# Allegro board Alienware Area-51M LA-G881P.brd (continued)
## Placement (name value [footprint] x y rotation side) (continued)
CT79  1U_0201_6.3V6M  [C_0201]  25.6 44.43 180 top
CT80  1U_0201_6.3V6M  [C_0201]  24.9 43.1 90 top
CT81  10U_0402_6.3V6M  [C_0402]  20.36 40.22 180 top
CT82  10U_0402_6.3V6M  [C_0402]  19.84 39.15 270 top
CT83  1U_0201_6.3V6M  [C_0201]  22.38 43.3 270 top
CT84  1U_0201_6.3V6M  [C_0201]  21.11 40.43 270 top
CT85  1U_0201_6.3V6M  [C_0201]  23.09 39.9 0 top
CT86  1U_0201_6.3V6M  [C_0201]  23.02 41.37 270 top
CT88  0.1U_0402_10V6K  [C_0402]  39.08 48.25 180 top
CT90  22U_0603_6.3V6M  [C_0603]  46.93 41.95 180 bottom
CT91  22U_0603_6.3V6M  [C_0603]  46.93 40.68 180 bottom
CT92  22U_0603_6.3V6M  [C_0603]  46.93 39.41 180 bottom
CT93  22U_0603_6.3V6M  [C_0603]  46.93 38.14 180 bottom
CT94  0.47U_0402_25V6K  [C_0402]  8.35 48.49 270 bottom
CT95  0.47U_0402_25V6K  [C_0402]  9.87 48.49 270 bottom
CT96  0.47U_0402_25V6K  [C_0402]  9.75 44.19 0 bottom
CT97  0.47U_0402_25V6K  [C_0402]  9.75 44.19 0 top
CT98  2.2U_0402_16V6K  [C_0402]  38.21 45.36 180 bottom
CT99  4.7U_0603_10V6K  [C_0603]  39.13 42.16 270 bottom
CT100  4.7U_0603_10V6K  [C_0603]  38.88 52.32 180 bottom
CT101  10U_0402_6.3V6M  [C_0402]  39.08 49.14 180 top
CT102  1U_0201_6.3V6M  [C_0201]  38.88 48.73 180 bottom
CT103  10U_0402_6.3V6M  [C_0402]  39.03 47.97 180 bottom
CT104  0.22U_0402_10V6K  [C_0402]  44.55 47.94 270 top
CT106  1U_0603_25V6K  [C_0603]  47.08 47.39 0 top
CT108  0.22U_0201_6.3V  [C_0201]  23.68 35.21 90 bottom
CT109  0.22U_0201_6.3V  [C_0201]  24.31 35.21 90 bottom
CT110  0.22U_0201_6.3V  [C_0201]  21.14 35.21 90 bottom
CT111  0.22U_0201_6.3V  [C_0201]  21.77 35.21 90 bottom
CT112  220P_0201_25V7K  [C_0201]  46.88 52.34 90 bottom
CT113  220P_0201_25V7K  [C_0201]  48.05 52.37 90 bottom
CT114  100P_0402_50V8J~D  [C_0402]  88.57 19.4 90 bottom
CT115  0.047U_0402_25V7K  [C_0402]  80.72 8.94 90 top
CT116  10U_0603_6.3V6M~D  [C_0603]  93.55 18.55 270 bottom
CT117  2200P_0402_25V7K  [C_0402]  93.44 19.44 90 bottom
CT118  0.1U_0402_10V6K  [C_0402]  94.67 18.64 270 bottom
CT121  0.1U_0402_16V7K  [C_0402]  60.34 23.58 0 top
CT122  4.7U_0805_10V4Z  [C_0805]  60.08 22.25 0 top
CT123  0.1U_0402_16V7K  [C_0402]  58.96 21.31 270 top
CT124  22U_0603_6.3V6M  [C_0603]  56.54 25.8 0 top
CT153  1U_0201_6.3V6M  [C_0201]  31.38 36.38 270 bottom
CT154  47U_0603_6.3V6M  [C_0603]  32.29 36.79 270 bottom
CT155  47U_0603_6.3V6M  [C_0603]  33.56 36.79 270 bottom
CT156  22P_0402_50V8J~D  [C_0402]  47.01 35.23 0 bottom
CT157  4.7U_0603_10V6K  [C_0603]  49.16 44.55 0 bottom
CT200  0.1U_0402_10V7K  [C_0402]  43.57 24.85 0 bottom
CT201  0.1U_0402_10V7K  [C_0402]  49.44 25.23 180 bottom
CT202  0.1U_0402_10V7K  [C_0402]  49.43 27.77 180 bottom
CT203  0.1U_0402_10V7K  [C_0402]  47.01 20.46 90 bottom
CT204  0.1U_0402_10V7K  [C_0402]  43.57 25.74 0 bottom
CT205  1U_0201_6.3V6M  [C_0201]  46.07 30.77 0 bottom
CT206  10U_0603_6.3V6M  [C_0603]  46.13 28.79 270 bottom
CT207  10U_0603_6.3V6M  [C_0603]  44.91 29.68 270 bottom
CT208  1U_0201_6.3V6M  [C_0201]  43.98 29.68 270 bottom
CT209  0.1U_0402_10V7K  [C_0402]  47.55 12.81 270 top
CT210  0.1U_0402_10V7K  [C_0402]  48.5 12.81 270 top
CT211  0.01U_0402_16V7K  [C_0402]  61.29 12.53 0 top
CT212  0.01U_0402_16V7K  [C_0402]  61.29 11.64 0 top
CT213  1U_0201_6.3V6M  [C_0201]  58.17 10.75 270 top
CT214  0.1U_0402_10V7K  [C_0402]  59.08 16.61 270 top
CT215  0.1U_0402_10V7K  [C_0402]  58.19 16.61 270 top
CT216  22U_0603_6.3V6M  [C_0603]  61.43 15.64 180 top
CT217  1U_0201_6.3V6M  [C_0201]  46.07 30.2 0 bottom
CT218  1U_0201_6.3V6M  [C_0201]  44.75 30.52 180 bottom
CT219  1U_0201_6.3V6M  [C_0201]  57.6 10.75 270 top
CT5361  0.1U_0402_10V6K  [C_0402]  283.65 82.06 90 top
CU2  47U_0805_6.3V6M  [C_0805]  25.3 18.22 90 bottom
CU3  10U_0603_6.3V6M~D  [C_0603]  23.81 18.58 90 bottom
CU6  150U_B2_6.3VM_R35M  [C_B2]  29.9 20.6 180 bottom
CU7  0.1U_0402_16V7K  [C_0402]  38.43 14.5 0 top
CU10  47U_0805_6.3V6M  [C_0805]  376.59 37.65 270 top
CU11  10U_0603_6.3V6M~D  [C_0603]  378.14 37.65 270 top
CU12  0.1U_0402_10V7K  [C_0402]  33.88 22.27 0 top
CU16  0.1U_0402_16V7K  [C_0402]  372.78 40.41 90 top
CU17  0.1U_0402_16V7K  [C_0402]  377.56 41.04 0 top
CU26  0.1U_0402_16V7K  [C_0402]  15.32 32.66 270 top
CU27  2.2U_0603_6.3V6K  [C_0603]  17.64 35.58 0 top
CU28  0.1U_0402_16V7K  [C_0402]  13.06 31.75 180 top
CU29  0.1U_0402_16V7K  [C_0402]  11.33 35.51 270 top
CU45  0.1U_0402_10V7K  [C_0402]  377.66 39.06 90 top
CU46  0.1U_0402_10V7K  [C_0402]  374.69 37.95 270 top
CU47  0.1U_0402_10V7K  [C_0402]  31.85 14.56 180 top
CU48  10U_0402_6.3V6M  [C_0402]  373.72 37.95 270 top
CU49  0.1U_0402_10V7K  [C_0402]  373.79 42.26 180 top
CU50  0.1U_0402_10V7K  [C_0402]  373.79 43.18 180 top
CU101  10P_0402_50V8J  [C_0402]  379.59 39.04 90 top
CU102  0.5P_0402_50V8  [C_0402]  378.62 39.04 90 top
CU104  3.3P_0201_25V8B  [C_0201]  373.66 38.95 90 bottom
CU105  3.3P_0201_25V8B  [C_0201]  374.04 22.08 90 bottom
CU106  0.1U_0402_10V7K  [C_0402]  373.86 21.25 180 top
CU107  0.1U_0402_10V7K  [C_0402]  373.85 22.18 180 top
CU108  0.1U_0402_16V7K  [C_0402]  32.16 28.85 270 top
CU109  0.01U_0402_16V7K  [C_0402]  25.99 20.03 0 top
CU110  0.1U_0402_10V7K  [C_0402]  33.91 23.21 0 top
CU111  0.1U_0402_10V7K  [C_0402]  34.82 24.18 180 top
CU112  0.1U_0402_10V7K  [C_0402]  34.82 25.09 180 top
CU113  0.1U_0402_10V7K  [C_0402]  23.42 23.06 0 top
CU114  0.1U_0402_10V7K  [C_0402]  23.42 23.98 0 top
CU242  0.5P_0402_50V8  [C_0402]  21.73 19.51 90 bottom
CU243  10P_0402_50V8J  [C_0402]  22.67 19.51 90 bottom
CU244  10P_0402_50V8J  [C_0402]  378.78 17.68 180 top
CU245  0.5P_0402_50V8  [C_0402]  378.78 18.64 180 top
CV19  0.1U_0402_10V7K  [C_0402]  179.74 134.45 90 top
CV21  4.7U_0805_10V4Z  [C_0805]  181.14 134.62 90 top
CV23  470P_0402_50V7K  [C_0402]  274.72 109.56 0 bottom
CV24  470P_0402_50V7K  [C_0402]  274.72 110.51 0 bottom
CV64  0.22U_0402_6.3V7K  [C_0402]  178.46 155.6 270 bottom
CV805  0.1U_0402_16V7K  [C_0402]  180.45 129.2 90 top
CV806  10U_0805_6.3V6M  [C_0805]  179.62 127.93 0 top
CV902  10U_0603_6.3V6M  [C_0603]  179.7 131.3 0 top
CV903  0.1U_0402_10V6K  [C_0402]  179.64 133.34 0 top
CV956  82P_0402_50V8J  [C_0402]  179.64 132.4 0 top
CV957  82P_0402_50V8J  [C_0402]  179.54 129.25 90 top
CV1071  10P_0402_50V8J  [C_0402]  299.36 42.62 90 bottom
CV1073  10P_0402_50V8J  [C_0402]  253.29 9.5 90 top
CV1074  10P_0402_50V8J  [C_0402]  48.02 45.84 0 top
CV1076  10P_0402_50V8J  [C_0402]  113.42 119.19 270 top
CV1078  0.1U_0402_10V7K  [C_0402]  114.34 119.21 270 top
CV1079  47U_0603_6.3V6M  [C_0603]  115.2 125.32 90 top
CV1080  10U_0603_6.3V6M  [C_0603]  111.66 120.55 180 top
CV1081  10U_0603_6.3V6M  [C_0603]  111.66 121.79 180 top
CV1082  10U_0603_6.3V6M  [C_0603]  116.39 125.32 90 top
CV1083  10P_0402_50V8J  [C_0402]  114.13 125.28 90 top
CV1084  0.1U_0402_10V7K  [C_0402]  112 125.33 90 top
CV1085  10U_0603_6.3V6M  [C_0603]  113.07 125.35 90 top
CV1086  0.22U_0402_6.3V7K  [C_0402]  177.57 155.6 270 bottom
CV1087  0.22U_0402_6.3V7K  [C_0402]  176.68 155.6 270 bottom
CV1088  0.22U_0402_6.3V7K  [C_0402]  175.79 155.6 270 bottom
CV1089  0.22U_0402_6.3V7K  [C_0402]  174.9 155.6 270 bottom
CV1090  0.22U_0402_6.3V7K  [C_0402]  174.01 155.6 270 bottom
CV1091  0.22U_0402_6.3V7K  [C_0402]  177.44 151.6 270 top
CV1092  0.22U_0402_6.3V7K  [C_0402]  176.55 151.6 270 top
CV1093  0.22U_0402_6.3V7K  [C_0402]  175.47 151.6 270 top
CV1094  0.22U_0402_6.3V7K  [C_0402]  174.59 151.6 270 top
CV1095  0.22U_0402_6.3V7K  [C_0402]  173.7 151.6 270 top
CV1096  0.22U_0402_6.3V7K  [C_0402]  172.81 151.6 270 top
CV1097  0.22U_0402_6.3V7K  [C_0402]  180.76 148.73 180 top
CV1098  0.22U_0402_6.3V7K  [C_0402]  180.76 147.84 180 top
CV1099  0.22U_0402_6.3V7K  [C_0402]  169.62 148.16 0 top
CV1100  0.22U_0402_6.3V7K  [C_0402]  169.62 149.05 0 top
CV1101  470P_0402_50V7K  [C_0402]  111.09 125.33 90 top
CV1102  2200P_0402_25V7K  [C_0402]  107.64 124.98 180 top
CV1103  10P_0402_50V8J  [C_0402]  107.65 118.3 270 top
CV1104  47U_0603_6.3V6M  [C_0603]  110.02 125.45 90 top
CV1105  10U_0603_6.3V6M  [C_0603]  108.76 118.79 270 top
CV1106  10U_0603_6.3V6M  [C_0603]  110 118.79 270 top
CV1107  10U_0603_6.3V6M  [C_0603]  108.75 125.45 90 top
CV1108  10P_0402_50V8J  [C_0402]  107.64 125.9 180 top
CV1109  470P_0402_50V7K  [C_0402]  117.96 126.2 0 bottom
DE1  SDMK0340L-7-F_SOD323-2~D  [SDMK0340L-7-F_SOD323-2]  354.51 23.99 90 top
DE2  -  [RB751V-40_SOD323-2]  308.13 28.06 180 top
DE3  -  [RB751V-40_SOD323-2]  288.21 7.94 90 top
DF1  -  [SDMK0340L-7-F_SOD323-2]  92.98 54.25 0 bottom
DF2  -  [SDMK0340L-7-F_SOD323-2]  377.19 48.65 270 bottom
DH1  -  [RB751V-40_SOD323-2]  270.05 72.03 0 top
DK1  -  [TVNST52302AB0_SOT523-3]  231.3 14.25 180 bottom
DK2  -  [TVNST52302AB0_SOT523-3]  227.05 14.64 180 bottom
DK3  -  [TVNST52302AB0_SOT523-3]  229.23 14.62 180 bottom
DN1  -  [RB751S40T1G_SOD523-2]  350.7 52.6 180 top
DN2  -  [RB751S40T1G_SOD523-2]  351.65 50.32 180 top
DS1  SDM10U45-7_SOD523-2~D  [RB520SM-30T2R_EMD2-2]  252.81 14.03 270 top
DT1  SDM10U45-7_SOD523-2~D  [RB520SM-30T2R_EMD2-2]  46.14 44.82 270 top
DT2  -  [PESD5V0H1BSF_SOD962-2-2]  11.02 41.93 270 bottom
DT3  -  [PESD5V0H1BSF_SOD962-2-2]  11.02 42.62 90 bottom
DT4  -  [PESD5V0H1BSF_SOD962-2-2]  11.02 41.93 270 top
DT5  -  [PESD5V0H1BSF_SOD962-2-2]  11.02 42.62 90 top
DT6  -  [PESD5V0H1BSF_SOD962-2-2]  13.08 48.38 90 top
DT7  -  [PESD5V0H1BSF_SOD962-2-2]  13.08 47.68 270 top
DT8  -  [PESD5V0H1BSF_SOD962-2-2]  13.08 48.38 90 bottom
DT9  -  [PESD5V0H1BSF_SOD962-2-2]  13.08 47.68 270 bottom
DT10  -  [TVWDF1004AD0_DFN9]  12.54 54.14 90 bottom
DT11  -  [PESD5V0H1BSF_SOD962-2-2]  11.33 45.44 270 bottom
DT12  -  [PESD5V0H1BSF_SOD962-2-2]  11.45 46.37 90 top
DT13  -  [PESD5V0H1BSF_SOD962-2-2]  11.45 46.37 90 bottom
DT14  -  [PESD5V0H1BSF_SOD962-2-2]  11.33 45.44 270 top
DT15  -  [PESD24VS2UT_SOT23-3]  52.29 49.75 90 top
DU2  -  [TVWDF1004AD0_DFN9]  22.18 21.83 90 top
DU6  -  [SDMK0340L-7-F_SOD323-2]  12.62 35.54 270 top
DU8  -  [SDMK0340L-7-F_SOD323-2]  20.45 33.27 180 top
DU9  -  [PESD5V0U2BT_SOT23-3]  26.09 15.87 90 top
DU10  -  [PESD5V0U2BT_SOT23-3]  377.34 39.14 270 bottom
DU11  -  [PESD5V0U2BT_SOT23-3]  377.81 22.38 270 bottom
DU12  -  [TVWDF1004AD0_DFN9]  375.96 44.23 270 top
DU13  -  [TVWDF1004AD0_DFN9]  375.89 23.5 270 top
FD1  FIDUCIAL  [FIDUCIAL_C40M80]  106.7 156.61 180 bottom
FD2  FIDUCIAL  [FIDUCIAL_C40M80]  106.72 156.69 0 top
FD10  FIDUCIAL  [FIDUCIAL_C40M80]  361.9 3.05 0 top
FD11  FIDUCIAL  [FIDUCIAL_C40M80]  361.92 3.07 180 bottom
H1  -  [H_3P8-G]  166.75 37.9 0 top
H2  -  [H_3P8-G]  183.06 18.4 0 top
H3  -  [H_3P8-G]  114.2 18.4 0 top
H4  -  [H_3P8-G]  119.85 103 0 top
H5  -  [H_3P8-G]  177.85 103 0 top
H8  -  [H_3P8-G]  148.75 98.96 0 top
H42  -  [H_3P8]  169.35 157.7 0 top
H43  -  [H_3P0-G]  108.2 137.5 0 top
H44  -  [H_3P0-G]  211.2 153 0 top
H45  -  [H_3P0-G]  6 55.1 0 top
H46  -  [H_3P0-G]  8.2 6.5 0 top
H47  -  [H_3P0-G]  4.5 36.1 0 top
H48  -  [H_3P0-G]  272.8 6.5 0 top
H49  -  [H_3P0-G]  192.2 6.5 0 top
H50  -  [H_3P0-G]  91.7 12 0 top
H51  -  [H_3P0-G]  307.2 63.5 0 top
H52  -  [H_3P0-G]  96.2 69.5 0 top
H53  -  [H_3P0-G]  290.2 106.7 0 top
H54  -  [H_3P0-G]  391.2 55.1 0 top
H55  -  [H_3P0-G]  395.2 6.5 0 top
H56  -  [H_3P2]  291.1 116 0 top
H57  -  [H_3P3]  331.3 16.64 0 top
H58  -  [H_3P2]  309.25 42.1 0 top
H59  -  [H_3P3]  281.3 16.64 0 top
H60  -  [H_3P2]  219 196 0 top
H63  -  [H_3P8]  191.7 196.1 0 top
H65  -  [H_3P8-G]  130.75 37.9 0 top
H70  -  [H_3P2]  166.7 118.7 0 top
H72  -  [H_3P0N]  11.2 11.5 0 top
H73  -  [H_4P0X3P0N]  272.7 12.5 0 top
J4  -  [JUMP_43X79]  342.52 17.23 90 top
J5  -  [JUMP_43X79]  342.59 25.39 270 top
J6  -  [JUMP_43X79]  273.16 88.03 0 top
JAUDIO  ACES_50473-0300M-P01  [ACES_50473-0300M-P01_30P]  42.56 14.76 180 bottom
JCDRA  TE_2260531-1  [TE_2260531-1_46P]  180.5 192.3 180 top
JDBG  CVILU_CH31052VA00-NH  [CVILU_CH31052VA00-NH_5P]  335.37 6.5 180 bottom
JDG  ACES_50293-0107N-P02  [ACES_50293-0107N-P02_10P]  283.95 105 180 bottom
JDGFF1  UNIMI_FBGCAX011  [UNIMI_FBGCAX011_68P-T]  177.87 125.64 90 bottom
JDGFF2  UNIMI_FBGCAX011  [UNIMI_FBGCAX011_68P-T]  177.87 140.64 90 bottom
JDIMM1  LOTES_ADDR0205-P001A02~D  [LOTES_ADDR0205-P001A02_260P]  245.58 26.78 90 bottom
JDIMM2  LOTES_ADDR0070-P025A~D  [LOTES_ADDR0070-P025A_260P]  218.7 26.78 270 bottom
JDIMM3  LOTES_ADDR0069-P009A  [LOTES_ADDR0069-P009A_260P-T]  231.58 26.78 90 bottom
JDIMM4  LOTES_ADDR0206-P001A02~D  [LOTES_ADDR0206-P001A02_260P]  204.7 26.78 270 bottom
JELC  CVILU_CH51102M100-0P  [CVILU_CH51102M100-0P_10P-T]  365.41 34.36 0 bottom
JFAN1  ACES_50273-0050N-001  [ACES_50273-0050N-001_5P]  88.47 57.43 41.1 bottom
JFAN2  ACES_50273-0050N-001  [ACES_50273-0050N-001_5P]  375.2 52.5 0 bottom
JFC  CVILUX CI1110M2VR0-NH 10P  [CVILU_CI1110M2VR0-NH_10P]  110.7 123.93 180 bottom
JHDD  ACES_50406-02071-001  [ACES_50406-02071-001_20P]  262.05 5.65 180 bottom
JLAN  SANTA_130456-931  [SANTA_130456-931_13P-T]  202.03 184.84 0 bottom
JP3  -  [JUMP_43X118]  256.23 10.21 180 top
JP6  -  [JUMP_43X118]  360.76 12.38 270 top
JPCMC  INTEL_CMC_PRIMARY  [INTEL_CMC_PRIMARY_36P-T]  61.02 48.01 0 top
JPK  ACES_51519-02001-P01  [ACES_51519-02001-P01_20P]  235.95 11.3 180 bottom
JPWR  ACES_50611-0060B-P01  [ACES_50611-0060B-P01_6P]  173.5 183.02 180 top
JRTC  ACES_50271-0020N-001  [ACES_50271-0020N-001_2P]  348.2 9.5 180 bottom
JSSD1  LOTES_APCI0096-P002A  [LOTES_APCI0096-P002A_75P]  363.62 7.4 90 bottom
JSSD2  LOTES_APCI0181-P001A  [LOTES_APCI0181-P001A_75P]  387.95 11.8 180 bottom
JTOBII  ACES_50228-0067N-001  [ACES_50228-0067N-001_6P]  294.69 40 270 bottom
JTP  ACES_51625-01601-001  [ACES_51625-01601-001_16P]  98.95 15.07 180 bottom
JTRON  ACES_50238-02471-002  [ACES_50238-02471-002_24P]  247.8 100.91 180 bottom
JUSB1  TAIWI_USB050-10B7CRL-TWD  [TAIWI_USB050-10B7CRL-TWD_10P-T]  17.18 26 90 bottom
JUSB2  ACON_TCRAY-9U1U91  [ACON_TCRAY-9U1U91_9P-T]  382.65 39 270 bottom
JUSB3  ACON_TCRAY-9U1U91  [ACON_TCRAY-9U1U91_9P-T]  382.65 19 270 bottom
JUSBC  JAE_DX07S024JJ5R1200~D  [JAE_DX07S024JJ5R1200_24P]  7.55 48.23 270 top
JWDB  ACES_88266-04001  [ACES_50207-00471-P01_4P-T]  295.42 5.83 180 top
JWLAN  LOTES_APCI0128-P005A  [LOTES_APCI0128-P005A_75P]  342.78 32.85 90 bottom
LE1  FBMA-L11-160808-800LMT_0603  [KC_FBMA-L11-160808-800LMT_2P]  312.66 9.24 180 top
LE2  FBMA-L11-160808-800LMT_0603  [KC_FBMA-L11-160808-800LMT_2P]  311.7 10.92 180 top
LE3  DLM0NSN900HY2D_4P  [MURAT_DLM0NSN900HY2D_4P]  297.33 42.56 180 bottom
LE4  BLM15AG121SN1D_L0402_2P  [MURAT_BLM15AG121SN1D_L0402_2P]  363.66 27.48 0 top
LE7  DLM0NSN900HY2D_4P  [MURAT_DLM0NSN900HY2D_4P]  234.52 13.48 180 bottom
LH1  2.2UH_FCI1608F_10%  [TDK_MLF1608A2R2KT_2P]  299.18 38.36 90 top
LH2  2.2UH_FCI1608F_10%  [TDK_MLF1608A2R2KT_2P]  265.14 40.36 270 top
LL1  1UH_AHP252010HF-1R0M_20%  [TAI-T_AHP252010HF-1R0M_2P]  192.52 162.27 180 top
LL2  1UH_AHP252010HF-1R0M_20%  [TAI-T_AHP252010HF-1R0M_2P]  172.27 167.2 90 top
LL4  1UH_AHP252010HF-1R0M_20%  [TAI-T_AHP252010HF-1R0M_2P]  165.61 162.96 0 top
LM1  DLM0NSN900HY2D_4P  [MURAT_DLM0NSN900HY2D_4P]  162.82 187.51 90 top
LT1  0.6UH_MND-04ABIR60M-XGL_20%  [MAG_MND-04ABIR60M-XGL_2P]  23.04 55.09 180 top
LT2  DLM0NSN900HY2D_4P  [MURAT_DLM0NSN900HY2D_4P]  16.14 54.63 180 bottom
LT3  DLM0NSN900HY2D_4P  [MURAT_DLM0NSN900HY2D_4P]  16.14 56.15 180 bottom
LT4  1UH_LQM18PN1R0MFHD_20%  [MURAT_LQM18PN1R0MFHD_2P]  35.28 36.81 90 bottom
LU3  DLM0NSN900HY2D_4P  [MURAT_DLM0NSN900HY2D_4P]  30.16 15.55 180 top
LU4  DLM0NSN900HY2D_4P  [MURAT_DLM0NSN900HY2D_4P]  372.03 38.95 0 bottom
LU5  DLM0NSN900HY2D_4P  [MURAT_DLM0NSN900HY2D_4P]  372.66 22.13 0 bottom
NOREF  -  []  148.75 98.96 0 top
NOREF#2  -  []  166.7 118.7 0 top
NOREF#3  -  []  176.36 -47.17 0 top
NOREF#4  -  []  119.85 103 0 top
NOREF#5  -  []  281.3 16.64 0 top
NOREF#6  -  []  130.75 37.96 0 top
NOREF#7  -  []  307.2 63.5 0 top
NOREF#8  -  []  114.2 18.4 0 top
NOREF#9  -  []  219 196 0 top
NOREF#10  -  []  175.05 131.05 0 top
NOREF#11  -  []  284.7 120.8 0 top
NOREF#12  -  []  91.7 12 0 top
NOREF#13  -  []  395.2 6.5 0 top
NOREF#14  -  []  183.06 18.4 0 top
NOREF#15  -  []  4.5 36.1 0 top
NOREF#16  -  []  193.31 86.22 0 top
NOREF#17  -  []  76.73 -208.51 0 top
NOREF#18  -  []  175.05 146.05 0 top
NOREF#19  -  []  191.7 196.1 0 top
NOREF#20  -  []  8.2 6.5 0 top
NOREF#21  -  []  193.72 69.37 0 top
NOREF#22  -  []  331.3 16.64 0 top
NOREF#23  -  []  99.34 -227.81 0 top
NOREF#24  -  []  291.1 116 0 top
NOREF#25  -  []  6 55.1 0 top
NOREF#26  -  []  177.85 103 0 top
NOREF#27  -  []  272.8 6.5 0 top
NOREF#28  -  []  169.35 157.7 0 top
NOREF#29  -  []  135.34 -111.04 0 top
NOREF#30  -  []  194.29 35.99 0 top
NOREF#31  -  []  166.75 37.96 0 top
NOREF#32  -  []  108.2 137.5 0 top
NOREF#33  -  []  309.25 42.1 0 top
NOREF#34  -  []  96.2 69.5 0 top
NOREF#35  -  []  391.2 55.1 0 top
NOREF#36  -  []  290.2 106.7 0 top
NOREF#37  -  []  192.2 6.5 0 top
NOREF#38  -  []  38.63 -199.62 0 top
NOREF#39  -  []  211.2 153 0 top
NOREF#40  -  []  259.78 101.01 0 top
NOREF#41  -  []  284.52 78.97 180 bottom
NOREF#42  -  []  188.26 -21.17 180 bottom
PBATT1  ACES_51481-01371-P01  [ACES_51481-01371-P01_13P]  66.6 13 0 bottom
PC1  2200P_0402_50V7K  [C_0402]  127.23 162.18 0 top
PC2  100P_0402_50V8J  [C_0402]  127.24 163.08 0 top
PC3  2200P_0402_50V7K  [C_0402]  118.44 168.35 90 top
PC4  100P_0402_50V8J  [C_0402]  117.23 168.31 90 top
PC5  2200P_0402_50V7K  [C_0402]  149.55 154.52 0 top
PC6  100P_0402_50V8J  [C_0402]  139.81 154.39 180 top
PC7  2200P_0402_50V7K  [C_0402]  140.3 151.01 270 top
PC8  100P_0402_50V8J  [C_0402]  141.82 151.01 270 top
PC9  0.022U_0402_25V7K  [C_0402]  73.73 21.51 270 bottom
PC10  0.01UF_0402_25V7K  [C_0402]  74.62 21.51 270 bottom
PC11  1000P_0402_50V7K  [C_0402]  64.29 17.87 270 bottom
PC12  100P_0402_50V8J  [C_0402]  65.17 17.87 270 bottom
PC13  .1U_0402_16V7K  [C_0402]  307.32 7.43 270 top
PC14  1U_0603_25V6K  [C_0603]  78 10.94 90 top
PC15  0.1U_0402_25V6  [C_0402]  149.07 159.49 90 bottom
PC16  0.1U_0402_25V6  [C_0402]  51.54 19.35 0 bottom
PC17  .1U_0402_16V7K  [C_0402]  58.93 21.12 270 bottom
PC18  0.22U_0603_25V7K  [C_0603]  54.63 22.01 90 bottom
PC19  3300P_0402_50V7-K  [C_0402]  121.06 153.9 270 top
PC20  3300P_0402_50V7-K  [C_0402]  126.76 154.46 0 bottom
PC21  3300P_0402_50V7-K  [C_0402]  153.85 154.72 0 top
PC22  3300P_0402_50V7-K  [C_0402]  153.85 153.81 0 top
PC23  1000P_0402_50V7K  [C_0402]  113.5 174.39 180 bottom
PC24  1000P_0402_50V7K  [C_0402]  149.43 150.77 0 top
PC25  0.1U_0402_25V6  [C_0402]  149.07 168.16 180 bottom
PC101  1000P_0402_50V7K  [C_0402]  274.78 18.92 270 top
PC102  0.1U_0402_25V6  [C_0402]  275.69 18.92 270 top
PC103  2200P_0402_50V7K  [C_0402]  273.86 18.92 270 top
PC104  10U_0603_25V6M  [C_0603]  275.81 21.89 0 top
PC105  10U_0603_25V6M  [C_0603]  275.81 20.19 0 top
PC106  1U_0402_25V6K  [C_0402]  272.95 18.92 270 top
PC107  0.1U_0603_25V7K  [C_0603]  268.44 9.27 180 top
PC108  0.1U_0402_16V7K  [C_0402]  260.59 9.14 180 top
PC109  1U_0603_6.3V6M  [C_0603]  266.85 8.09 270 top
PC110  220U 2.5V Y D2 ESR9M H1.9 SX  [C_D2]  262.46 24.56 0 top
PC111  220U 2.5V Y D2 ESR9M H1.9 SX  [C_D2]  262.41 29.26 0 top
PC112  680P_0402_50V7K  [C_0402]  270.84 16.6 0 bottom
PC200  0.1U_0402_25V6  [C_0402]  232.31 120.43 90 top
PC201  2200P_0402_50V7K  [C_0402]  233.2 120.43 90 top
PC202  10U_0603_25V6M  [C_0603]  225.78 120.23 90 top
PC203  10U_0603_25V6M  [C_0603]  226.98 120.23 90 top
PC204  0.1U_0603_25V7K  [C_0603]  219.75 121.41 270 top
PC205  10U_0603_6.3V6M  [C_0603]  212.08 118.29 90 top
PC206  10U_0603_6.3V6M  [C_0603]  213.82 118.29 90 top
PC207  1U_0603_10V6K  [C_0603]  223.61 113.88 180 top
PC208  1U_0402_25V6K  [C_0402]  231.42 120.42 90 top
PC209  220U 2.5V Y D2 ESR9M H1.9 SX  [C_D2]  257.73 114.29 90 top
PC210  0.033U_0402_16V7K  [C_0402]  214.16 116.76 180 top
PC211  680P_0402_50V7K  [C_0402]  237.07 113.35 270 top
PC212  2.2U_0402_6.3V6M  [C_0402]  221.07 113.89 270 top
PC213  0.1U_0402_10V7K  [C_0402]  217.77 113.79 270 top
PC214  0.1U_0402_10V7K  [C_0402]  216.88 113.79 270 top
PC215  220U 2.5V Y D2 ESR9M H1.9 SX  [C_D2]  262.5 114.3 90 top
PC216  1000P_0402_50V7K  [C_0402]  230.52 120.42 90 top
PC217  0.1U_0402_25V6  [C_0402]  216.62 109.48 270 top
PC218  0.1U_0402_25V6  [C_0402]  212.83 111.33 270 top
PC219  10U_0603_25V6M  [C_0603]  228.18 120.25 90 top
PC220  10U_0603_25V6M  [C_0603]  229.38 120.26 90 top
PC301  1U_0402_25V6K  [C_0402]  313.87 39.37 180 top
PC302  4.7U_0402_6.3V6M  [C_0402]  332.19 38.5 0 top
PC303  22U_0805_25V6M  [C_0805]  317.77 39.67 0 top
PC304  22U_0805_25V6M  [C_0805]  312.04 36.01 270 top
PC305  1000P_0402_50V7K  [C_0402]  313.33 35.47 270 top
PC306  0.1U_0402_25V6  [C_0402]  312.14 37.64 90 top
PC307  2200P_0402_50V7K  [C_0402]  318.15 38.31 0 top
PC308  22U_0805_25V6M  [C_0805]  310.31 35.99 270 top
PC309  22U_0805_25V6M  [C_0805]  317.74 41.37 0 top
PC310  0.1U_0402_25V6  [C_0402]  329.48 41.77 90 top
PC311  0.1U_0402_25V6  [C_0402]  329.49 34.06 90 top
PC312  220U_D2_6.3VY_R15M  [C_D2]  327.18 45.3 90 top
PC313  220U_D2_6.3VY_R15M  [C_D2]  331.88 45.3 90 top
PC314  220U_D2_6.3VY_R15M  [C_D2]  324.56 21.42 180 top
PC315  220U_D2_6.3VY_R15M  [C_D2]  329.41 24.41 90 top
PC316  680P_0603_50V8J  [C_0603]  309.46 47.84 270 top
PC317  680P_0603_50V8J  [C_0603]  310.79 31.1 270 top
PC318  4.7U_0402_6.3V6M  [C_0402]  326.03 38.5 180 top
PC319  4.7U_0402_6.3V6M  [C_0402]  326.64 14.27 0 top
PC705  2200P_0402_50V7K  [C_0402]  196.3 158.28 270 bottom
PC708  0.1U_0402_25V6  [C_0402]  205.77 144.08 180 top
PC711  0.01UF_0402_25V7K  [C_0402]  211.56 137.31 180 top
PC721  0.47U_0402_25V6K  [C_0402]  201.52 138.81 0 top
PC747  0.1U_0402_25V6  [C_0402]  208.23 136.04 0 top
PC748  0.1U_0402_25V7K  [C_0402]  213.05 141.25 0 top
PC749  2200P_0402_25V7K  [C_0402]  213.97 142.14 180 top
PC750  0.22U_0603_25V7K  [C_0603]  205.76 136.23 270 top
PC751  560P_0402_50V7K  [C_0402]  209.97 144.02 180 top
PC752  0.033U_0402_25V7K  [C_0402]  211.67 145.71 270 top
PC753  10P_0402_50V8J  [C_0402]  207.73 145.74 90 top
PC757  1U_0603_25V6  [C_0603]  202.24 141.66 0 top
PC760  10U_0603_25V6M  [C_0603]  197.38 158.33 270 bottom
PC761  10U_0603_25V6M  [C_0603]  198.86 135.04 0 top
PC762  10U_0603_25V6M  [C_0603]  198.59 158.33 270 bottom
PC763  10U_0603_25V6M  [C_0603]  198.59 158.33 270 top
PC764  10U_0603_25V6M  [C_0603]  197.38 158.33 270 top
PC765  0.1U_0402_25V6  [C_0402]  195.41 158.28 270 bottom
PC766  10U_0603_25V6M  [C_0603]  193.84 132.32 180 top
PC767  1000P_0603_50V7K  [C_0603]  192.37 154.14 0 bottom
PC768  2.2U_0402_16V6K  [C_0402]  200.44 140.86 0 top
PC769  2.2U_0402_16V6K  [C_0402]  200.44 139.97 0 top
PC775  10U_0603_25V6M  [C_0603]  198.86 136.25 0 top
PC776  10U_0603_25V6M  [C_0603]  193.84 130.61 180 top
PC777  0.1U_0402_25V7K  [C_0402]  198.79 137.31 0 top
PC778  10U_0603_25V6M  [C_0603]  198.87 138.36 0 top
PC779  0.1U_0402_25V7K  [C_0402]  192.68 142.31 90 bottom
PC780  1000P_0402_25V8J  [C_0402]  196.3 158.28 270 top
PC781  1000P_0402_25V8J  [C_0402]  195.41 158.28 270 top
PC791  1000P_0402_25V8J  [C_0402]  207.16 136.12 270 top
PC792  0.033U_0402_25V7K  [C_0402]  208.99 134.07 0 top
PC793  0.01U_0402_25V7K  [C_0402]  208.13 134.07 180 top
PC794  2200P_0402_50V7K  [C_0402]  199.67 158.33 270 top
PC795  10U_0603_25V6M  [C_0603]  193.83 129.28 180 top
PC796  10U_0603_25V6M  [C_0603]  193.82 128.04 180 top
PC797  100U_D3L_25VM_R60M  [C_T521D107M025ATE060]  273.21 115.34 180 top
PC798  100U_D3L_25VM_R60M  [C_T521D107M025ATE060]  273.21 120.17 180 top
PC800  100U_D3L_25VM_R60M  [C_T521D107M025ATE060]  277.59 113.51 270 top
PC1201  22U_0603_6.3V6M  [C_0603]  367.82 50.01 270 bottom
PC1202  680P_0402_50V7K  [C_0402]  358.72 48.49 180 top
PC1203  1U_0402_6.3V6K  [C_0402]  359.38 48.11 180 bottom
PC1204  100P_0402_50V8J  [C_0402]  354.94 53.26 0 bottom
PC1205  22U_0805_25V6M  [C_0805]  369.21 51.57 90 bottom
PC1206  0.01U_0402_50V7K  [C_0402]  356.2 49.71 180 bottom
PC1207  330P_0402_50V8J  [C_0402]  354.18 50.7 180 bottom
PC1208  22U_0805_25V6M  [C_0805]  369.21 51.57 90 top
PC1801  22P_0402_50V8J  [C_0402]  302.41 33.78 270 bottom
PC1802  22U_0603_6.3V6M  [C_0603]  293.08 34.06 180 top
PC1803  22U_0603_6.3V6M  [C_0603]  300.57 37.06 180 top
PC1804  22U_0603_6.3V6M  [C_0603]  293.14 35.14 180 bottom
PC1805  0.1U_0402_16V7K  [C_0402]  293.15 32.28 180 bottom
PC1806  22U_0603_6.3V6M  [C_0603]  300.6 36.7 180 bottom
PC1807  2.2U_0402_6.3V6K  [C_0402]  295.41 36.6 0 bottom
PC2501  0.1U_0402_16V7K  [C_0402]  243.77 18.15 270 bottom
PC2502  22U_0603_6.3V6M  [C_0603]  243.47 15.97 0 bottom
PC2503  22U_0603_6.3V6M  [C_0603]  243.45 14.73 0 bottom
PC2504  22P_0603_50V8  [C_0603]  233.61 16.92 90 bottom
PC2505  22U_0603_6.3V6M  [C_0603]  233.22 15.95 270 bottom
PC2506  22U_0603_6.3V6M  [C_0603]  234.42 15.95 270 bottom
PC2507  2.2U_0402_6.3V6K  [C_0402]  240.64 13.51 180 bottom
PCA01  1000P_0402_50V7K  [C_0402]  137.38 118.4 270 top
PCA02  0.1U_0402_25V6  [C_0402]  137.43 118.39 270 bottom
PCA03  2200P_0402_50V7K  [C_0402]  136.49 118.4 270 top
PCA04  10U_0603_25V6M  [C_0603]  137.27 119.68 90 top
PCA05  10U_0603_25V6M  [C_0603]  136.08 119.68 90 top
PCA06  10U_0603_25V6M  [C_0603]  136.08 119.68 90 bottom
PCA07  1U_0402_25V6K  [C_0402]  136.52 118.4 270 bottom
PCA08  4.7U_0402_10V6M  [C_0402]  129.77 112.72 270 bottom
PCA09  4.7U_0402_10V6M  [C_0402]  131.55 112.75 270 bottom
PCA10  0.1U_0603_25V7K  [C_0603]  132.52 115.72 0 bottom
PCA11  6800P_0402_25V7K  [C_0402]  135.53 112.57 0 bottom
PCA12  680P_0603_50V7K  [C_0603]  147.95 119.95 270 bottom
PCA13  0.01U_0402_25V7K  [C_0402]  125.15 116.78 180 bottom
PCA14  1000P_0402_50V7K  [C_0402]  135.53 113.49 0 bottom
PCA15  47U_0805_6.3V6M  [C_0805]  146.29 75.07 0 top
PCA16  47U_0805_6.3V6M  [C_0805]  146.44 73.34 0 top
PCA17  47U_0805_6.3V6M  [C_0805]  145.15 76.16 180 top
PCA18  47U_0805_6.3V6M  [C_0805]  146.3 76.79 0 top
PCA19  22U_0603_6.3V6M  [C_0603]  145.19 74.7 180 top
PCA20  22U_0603_6.3V6M  [C_0603]  150.27 76.6 0 top
PCA21  22U_0603_6.3V6M  [C_0603]  149.19 76.1 270 top
PCA22  22U_0603_6.3V6M  [C_0603]  125.54 99.69 225 top
PCA23  22U_0603_6.3V6M  [C_0603]  126.65 99.1 225 top
PCA24  22U_0603_6.3V6M  [C_0603]  127.52 98.25 225 top
PCA25  10U_0603_25V6M  [C_0603]  137.27 119.68 90 bottom
PCA26  0.1U_0402_16V7K  [C_0402]  131.66 117.68 90 top
PCF01  2200P_0402_50V7K  [C_0402]  154.48 117.13 90 top
PCF02  0.1U_0402_25V6  [C_0402]  155.38 117.14 90 top
PCF03  10U_0603_25V6M  [C_0603]  153.66 116.1 0 bottom
PCF04  1U_0402_25V6K  [C_0402]  154.49 117.13 90 bottom
PCF05  1000P_0402_50V7K  [C_0402]  154.52 116.27 0 top
PCF06  0.1U_0603_25V7K  [C_0603]  151.11 110.66 0 bottom
PCF07  22U_0603_6.3V6M  [C_0603]  158.18 105.69 270 bottom
PCF08  22U_0603_6.3V6M  [C_0603]  159.4 106.78 90 bottom
PCF09  22U_0603_6.3V6M  [C_0603]  159.4 105.69 270 bottom
PCF10  22U_0603_6.3V6M  [C_0603]  158.18 106.78 90 bottom
PCF11  330P_0402_50V7K  [C_0402]  161.32 110.5 90 bottom
PCF12  0.22U_0402_10V6K  [C_0402]  157.87 115.41 0 bottom
PCF13  4.7U_0402_6.3V6M  [C_0402]  157.62 109.51 0 bottom
PCF14  680P_0603_50V7K  [C_0603]  152.35 105.46 270 bottom
PCF15  2.2U_0402_6.3V6M  [C_0402]  159.53 110.45 0 bottom
PCG01  1U_0402_6.3V6K  [C_0402]  127.98 11.95 90 top
PCG02  1U_0402_6.3V6K  [C_0402]  131.77 16.03 0 bottom
PCG03  0.22U_0603_16V7K  [C_0603]  127.09 11.53 90 bottom
PCG04  10U_0603_25V6M  [C_0603]  124.7 12.8 270 top
PCG05  10U_0603_25V6M  [C_0603]  124.7 12.8 270 bottom
PCG06  10U_0603_25V6M  [C_0603]  123.51 12.78 270 top
PCG07  0.1U_0402_25V6  [C_0402]  142.22 13.65 180 top
PCG08  2200P_0402_50V7K  [C_0402]  142.25 14.58 180 bottom
PCG09  1U_0402_25V6K  [C_0402]  124.25 16.44 180 bottom
PCG10  1000P_0402_50V7K  [C_0402]  124.25 14.66 180 bottom
PCG11  680P_0603_50V7K  [C_0603]  137.82 14.63 0 bottom
PCG12  1U_0402_6.3V6K  [C_0402]  151.54 15.12 90 bottom
PCG13  1U_0402_6.3V6K  [C_0402]  147.71 13.04 0 top
PCG14  0.22U_0603_16V7K  [C_0603]  147.3 11.7 90 bottom
PCG15  10U_0603_25V6M  [C_0603]  123.51 12.78 270 bottom
PCG16  10U_0603_25V6M  [C_0603]  143.68 13.21 270 bottom
PCG17  0.1U_0402_25V6  [C_0402]  124.24 15.55 180 bottom
PCG18  2200P_0402_50V7K  [C_0402]  124.25 13.77 180 bottom
PCG19  1000P_0402_50V7K  [C_0402]  142.22 13.65 180 bottom
PCG20  680P_0603_50V7K  [C_0603]  161.22 17.39 180 bottom
PCG21  10U_0603_25V6M  [C_0603]  143.71 13.21 270 top
PCG22  1U_0402_25V6K  [C_0402]  142.22 12.75 180 bottom
PCG23  470U_D2_2VM_R4.5M  [C_D2]  160.25 28.77 0 top
PCG24  470U_D2_2VM_R4.5M  [C_D2]  150.14 28.78 0 top
PCG25  470U_D2_2VM_R4.5M  [C_D2]  148.88 22.82 180 bottom
PCG26  470U_D2_2VM_R4.5M  [C_D2]  139.37 28.9 0 top
PCG27  47U_0805_6.3V6M  [C_0805]  149.11 50.84 180 top
PCG28  47U_0805_6.3V6M  [C_0805]  150.23 52.59 0 top
PCG29  47U_0805_6.3V6M  [C_0805]  150.23 54.29 0 top
PCG30  47U_0805_6.3V6M  [C_0805]  144.56 52.59 0 top
PCG31  47U_0805_6.3V6M  [C_0805]  155.19 52.35 180 top
PCG32  47U_0805_6.3V6M  [C_0805]  144.56 54.29 0 top
PCG33  47U_0805_6.3V6M  [C_0805]  150.25 50.82 0 top
PCG34  47U_0805_6.3V6M  [C_0805]  149.11 54.29 180 top
PCG35  47U_0805_6.3V6M  [C_0805]  149.11 52.59 180 top
PCG36  47U_0805_6.3V6M  [C_0805]  155.19 54.06 180 top
PCG37  47U_0805_6.3V6M  [C_0805]  144.56 50.84 0 top
PCG38  10U_0603_25V6M  [C_0603]  144.88 13.21 270 bottom
PCG39  10U_0603_25V6M  [C_0603]  144.91 13.21 270 top
PCI06  1U_0402_6.3V6K  [C_0402]  105.5 31.19 90 top
PCI07  1U_0402_6.3V6K  [C_0402]  101.64 32.37 0 top
PCI08  0.22U_0603_16V7K  [C_0603]  100.91 33.39 0 bottom
PCI09  1U_0402_25V6K  [C_0402]  114.86 95.06 270 bottom
PCI10  1000P_0402_50V7K  [C_0402]  115.76 95.06 270 bottom
PCI11  100U_25V_M  [C_ECST250ADA101MF611]  97.04 39.97 0 bottom
PCI12  10U_0603_25V6M  [C_0603]  102.34 37.66 180 top
PCI13  10U_0603_25V6M  [C_0603]  102.34 37.66 180 bottom
PCI14  10U_0603_25V6M  [C_0603]  103.55 37.86 0 bottom
PCI15  0.1U_0402_25V6  [C_0402]  102.36 35.69 180 bottom
PCI16  2200P_0402_50V7K  [C_0402]  102.37 36.6 180 bottom
PCI17  33P_0603_50V8J  [C_0603]  109.3 31.17 180 top
PCI18  1U_0402_6.3V6K  [C_0402]  105.31 22.17 90 top
PCI19  1U_0402_6.3V6K  [C_0402]  101.42 23.33 0 bottom
PCI20  0.22U_0603_16V7K  [C_0603]  100.86 24.41 0 bottom
PCI21  100U_25V_M  [C_ECST250ADA101MF611]  97.04 25.75 0 bottom
PCI25  0.1U_0402_25V6  [C_0402]  101.99 26.68 180 bottom
PCI26  2200P_0402_50V7K  [C_0402]  101.91 28.84 180 bottom
PCI27  1U_0402_25V6K  [C_0402]  101.99 26.67 180 top
PCI28  1000P_0402_50V7K  [C_0402]  101.91 28.84 180 top
PCI29  33P_0603_50V8J  [C_0603]  107.96 20.55 0 bottom
PCI35  1U_0402_6.3V6K  [C_0402]  106.96 59.26 90 top
PCI36  1U_0402_6.3V6K  [C_0402]  102.95 59.33 0 bottom
PCI37  0.22U_0603_16V7K  [C_0603]  104.47 60.42 0 bottom
PCI38  10U_0603_25V6M  [C_0603]  105.85 64.05 180 top
PCI39  10U_0603_25V6M  [C_0603]  105.85 64.05 180 bottom
PCI40  10U_0603_25V6M  [C_0603]  105.87 62.85 180 bottom
PCI41  0.1U_0402_25V6  [C_0402]  107.75 65.94 0 bottom
PCI42  2200P_0402_50V7K  [C_0402]  107.75 65.05 0 bottom
PCI43  1U_0402_25V6K  [C_0402]  107.75 66.85 0 bottom
PCI44  1000P_0402_50V7K  [C_0402]  107.75 64.13 0 bottom
PCI45  33P_0603_50V8J  [C_0603]  116.52 65.35 180 bottom
PCI46  1U_0402_6.3V6K  [C_0402]  110.69 67.65 0 bottom
PCI47  0.22U_0603_16V7K  [C_0603]  106.32 72.18 0 bottom
PCI48  1U_0402_6.3V6K  [C_0402]  105.37 72.74 270 bottom
PCI49  10U_0603_25V6M  [C_0603]  110.45 75.59 0 bottom
PCI50  10U_0603_25V6M  [C_0603]  110.45 76.79 0 bottom
PCI51  10U_0603_25V6M  [C_0603]  110.45 78 0 bottom
PCI52  0.1U_0402_25V6  [C_0402]  109.15 77.92 180 bottom
PCI53  2200P_0402_50V7K  [C_0402]  109.16 77.02 180 bottom
PCI54  1U_0402_25V6K  [C_0402]  109.15 76.13 180 bottom
PCI55  1000P_0402_50V7K  [C_0402]  111.01 80.29 0 bottom
PCI56  33P_0603_50V8J  [C_0603]  118.86 77.37 90 top
PCI62  1U_0402_6.3V6K  [C_0402]  105.31 40.46 90 top
PCI63  1U_0402_6.3V6K  [C_0402]  101.64 42.23 0 top
PCI64  0.22U_0603_16V7K  [C_0603]  101.04 43.22 0 bottom
PCI65  10U_0603_25V6M  [C_0603]  104.21 47.44 0 bottom
PCI66  10U_0603_25V6M  [C_0603]  104.21 47.44 0 top
PCI67  10U_0603_25V6M  [C_0603]  101.98 47.46 180 top
PCI68  0.1U_0402_25V6  [C_0402]  101.91 45.52 180 bottom
PCI69  2200P_0402_50V7K  [C_0402]  101.9 46.41 180 bottom
PCI70  1U_0402_25V6K  [C_0402]  101.9 46.41 180 top
PCI71  1000P_0402_50V7K  [C_0402]  101.91 45.51 180 top
PCI72  33P_0603_50V8J  [C_0603]  107.67 40.61 180 top
PCI73  1U_0402_6.3V6K  [C_0402]  106.06 49.24 0 top
PCI74  1U_0402_6.3V6K  [C_0402]  106.08 50.95 180 top
PCI75  0.22U_0603_16V7K  [C_0603]  102.59 51.96 0 bottom
PCI76  10U_0603_25V6M  [C_0603]  103.96 54.42 180 top
PCI77  10U_0603_25V6M  [C_0603]  105.5 56.28 0 bottom
PCI78  10U_0603_25V6M  [C_0603]  105.5 56.28 0 top
PCI79  0.1U_0402_25V6  [C_0402]  103.46 55.47 180 bottom
PCI80  2200P_0402_50V7K  [C_0402]  103.45 56.36 180 bottom
PCI81  1U_0402_25V6K  [C_0402]  103.45 56.36 180 top
PCI82  1000P_0402_50V7K  [C_0402]  103.45 55.47 180 top
PCI83  33P_0603_50V8J  [C_0603]  114.05 55.33 180 bottom
PCI86  470U_D2_2VM_R4.5M  [C_D2]  125.65 28.86 0 top
PCI87  470U_D2_2VM_R4.5M  [C_D2]  155.82 62.18 90 top
PCI88  470U_D2_2VM_R4.5M  [C_D2]  141.66 58.52 270 top
PCI89  470U_D2_2VM_R4.5M  [C_D2]  141.67 62.58 90 top
PCI90  470U_D2_2VM_R4.5M  [C_D2]  146.38 62.15 90 top
PCI91  470U_D2_2VM_R4.5M  [C_D2]  122.76 22.84 0 bottom
PCI92  470U_D2_2VM_R4.5M  [C_D2]  120.56 18.44 270 bottom
PCI93  470U_D2_2VM_R4.5M  [C_D2]  121.81 64.34 90 top
PCI94  470U_D2_2VM_R4.5M  [C_D2]  121.81 60.29 270 top
PCI95  470U_D2_2VM_R4.5M  [C_D2]  121.81 74.29 90 top
PCI96  47U_0805_6.3V6M  [C_0805]  157.13 70.67 90 top
PCI97  47U_0805_6.3V6M  [C_0805]  152.92 67.75 90 bottom
PCI98  47U_0805_6.3V6M  [C_0805]  151.22 67.75 90 bottom
PCI99  47U_0805_6.3V6M  [C_0805]  151.15 66.34 270 bottom
PCI100  47U_0805_6.3V6M  [C_0805]  149.52 67.75 90 bottom
PCI101  47U_0805_6.3V6M  [C_0805]  146.11 67.73 90 bottom
PCI102  47U_0805_6.3V6M  [C_0805]  144.41 67.73 90 bottom
PCI103  47U_0805_6.3V6M  [C_0805]  144.3 66.34 270 bottom
PCI104  47U_0805_6.3V6M  [C_0805]  147.82 67.73 90 bottom
PCI105  47U_0805_6.3V6M  [C_0805]  144.38 55.74 90 bottom
PCI106  47U_0805_6.3V6M  [C_0805]  146.09 55.74 90 bottom
PCI107  47U_0805_6.3V6M  [C_0805]  147.79 55.74 90 bottom
PCI108  47U_0805_6.3V6M  [C_0805]  152.89 55.74 90 bottom
PCI109  47U_0805_6.3V6M  [C_0805]  151.19 55.74 90 bottom
PCI110  47U_0805_6.3V6M  [C_0805]  149.49 55.74 90 bottom
PCI111  47U_0805_6.3V6M  [C_0805]  155.69 71.02 180 top
PCI112  47U_0805_6.3V6M  [C_0805]  144.38 60.26 270 bottom
PCI113  47U_0805_6.3V6M  [C_0805]  152.89 60.26 270 bottom
PCI114  47U_0805_6.3V6M  [C_0805]  151.19 60.26 270 bottom
PCI115  47U_0805_6.3V6M  [C_0805]  149.49 60.26 270 bottom
PCI116  47U_0805_6.3V6M  [C_0805]  147.79 60.26 270 bottom
PCI117  47U_0805_6.3V6M  [C_0805]  146.09 60.26 270 bottom
PCI118  47U_0805_6.3V6M  [C_0805]  146.01 61.78 90 bottom
PCI119  47U_0805_6.3V6M  [C_0805]  144.3 61.78 90 bottom
PCI120  47U_0805_6.3V6M  [C_0805]  125.09 25.61 0 top
PCI121  47U_0805_6.3V6M  [C_0805]  144.17 72.41 270 bottom
PCI122  47U_0805_6.3V6M  [C_0805]  145.89 72.41 270 bottom
PCI123  47U_0805_6.3V6M  [C_0805]  152.87 66.34 270 bottom
PCI124  47U_0805_6.3V6M  [C_0805]  147.73 61.78 90 bottom
PCI125  47U_0805_6.3V6M  [C_0805]  149.44 61.78 90 bottom
PCI126  47U_0805_6.3V6M  [C_0805]  151.15 61.78 90 bottom
PCI127  47U_0805_6.3V6M  [C_0805]  152.87 61.78 90 bottom
PCI128  47U_0805_6.3V6M  [C_0805]  153.6 70.89 180 bottom
PCI129  22U_0805_10V6M  [C_0805]  153.92 59.53 270 top
PCI130  22U_0805_10V6M  [C_0805]  149.44 66.34 270 bottom
PCI131  22U_0805_10V6M  [C_0805]  155.62 59.53 270 top
PCI132  22U_0805_10V6M  [C_0805]  147.73 66.34 270 bottom
PCI133  22U_0805_10V6M  [C_0805]  146.01 66.34 270 bottom
PCI134  22U_0603_6.3V6M  [C_0603]  157.14 59.62 270 top
PCI135  22U_0603_6.3V6M  [C_0603]  122.58 65.43 90 bottom
PCI136  22U_0603_6.3V6M  [C_0603]  119.97 30.19 90 bottom
PCI137  22U_0603_6.3V6M  [C_0603]  121.31 47.46 180 bottom
PCI138  22U_0603_6.3V6M  [C_0603]  122.64 55.08 90 bottom
PCI139  10U_0603_25V6M  [C_0603]  103.55 37.86 0 top
PCI140  100U_25V_M  [C_ECST250ADA101MF611]  97.04 32.86 0 bottom
PCI141  10U_0603_25V6M  [C_0603]  103.07 28.85 0 bottom
PCI142  10U_0603_25V6M  [C_0603]  105.87 62.85 180 top
PCI143  10U_0603_25V6M  [C_0603]  110.45 79.21 0 bottom
PCI144  10U_0603_25V6M  [C_0603]  101.98 47.46 180 bottom
PCI145  10U_0603_25V6M  [C_0603]  103.96 54.42 180 bottom
PCI146  10U_0603_25V6M  [C_0603]  101.93 27.72 180 bottom
PCI147  10U_0603_25V6M  [C_0603]  103.07 28.85 0 top
PCI148  10U_0603_25V6M  [C_0603]  101.93 27.72 180 top
PCI149  470U_D2_2VM_R4.5M  [C_D1]  145.42 57.65 0 top
PCI150  470U_D2_2VM_R4.5M  [C_D1]  151.11 62.44 90 top
PCI201  47P_0402_50V8J  [C_0402]  86.71 28.87 180 top
PCI202  47P_0402_50V8J  [C_0402]  86.74 27.55 180 top
PCI203  2.2U_0402_16V6K  [C_0402]  89.22 26.75 180 bottom
PCI204  1U_0402_6.3V6K  [C_0402]  82.3 42.86 180 bottom
PCI205  2.2U_0402_16V6K  [C_0402]  89.05 29.21 180 bottom
PCI206  1U_0402_6.3V6K  [C_0402]  82.35 29.09 180 bottom
PCI207  2.2U_0402_16V6K  [C_0402]  89.11 41.05 180 bottom
PCI208  47P_0402_50V8J  [C_0402]  86.74 43.02 180 top
PCI209  2.2U_0402_16V6K  [C_0402]  89.13 43.53 180 bottom
PCI210  47P_0402_50V8J  [C_0402]  86.76 41.7 180 top
PCI211  1U_0402_6.3V6K  [C_0402]  82.21 36.49 180 bottom
PCI212  2.2U_0402_16V6K  [C_0402]  89.01 34.67 180 bottom
PCI213  47P_0402_50V8J  [C_0402]  86.64 36.65 180 top
PCI214  2.2U_0402_16V6K  [C_0402]  89.03 37.16 180 bottom
PCI215  47P_0402_50V8J  [C_0402]  86.66 35.32 180 top
PCS01  10U_0603_25V6M  [C_0603]  106.09 145.94 270 top
PCS02  10U_0603_25V6M  [C_0603]  107.28 145.94 270 top
PCS03  22U_B2_25VM_R100M  [C_B2]  106.75 147.86 270 top
PCS04  10U_0603_25V6M  [C_0603]  127.82 138.32 180 top
PCS05  10U_0603_25V6M  [C_0603]  127.82 137.13 180 top
PCS06  22U_B2_25VM_R100M  [C_B2]  127.78 134.74 0 top
PCS19  4.7U_0402_6.3V6M  [C_0402]  122.17 146.56 270 top
PCS20  1U_0402_25V6K  [C_0402]  121.2 146.64 180 top
PCS21  1U_0402_25V6K  [C_0402]  121.2 145.69 180 top
PCS22  0.22U_0402_25V6K  [C_0402]  121.17 144.97 0 bottom
PCS23  1U_0402_25V6K  [C_0402]  124.09 148.6 90 top
PCS24  1U_0402_6.3V6K  [C_0402]  123.23 141.54 270 bottom
PCS25  1U_0402_6.3V6K  [C_0402]  125.21 149.85 270 top
PCS26  0.22U_0402_25V6K  [C_0402]  126.54 141.2 270 bottom
PCS27  560P_0402_50V7K  [C_0402]  129.68 145.53 0 top
PCS28  1000P_0402_50V7K  [C_0402]  129.81 144.71 0 bottom
PCS29  0.022U_0603_50V7K  [C_0603]  130.13 146.42 90 bottom
PCS30  10U_0603_25V6M  [C_0603]  130.34 140.89 180 bottom
PCS31  10U_0603_25V6M  [C_0603]  137.7 124.06 90 bottom
PCS32  10U_0603_25V6M  [C_0603]  138.91 124.06 90 bottom
PCS42  10U_0603_25V6M  [C_0603]  130.34 139.69 180 bottom
PCS48  4.7U_0402_6.3V6M  [C_0402]  143.97 143.61 270 top
PCS49  1U_0402_25V6K  [C_0402]  144.44 144.68 180 top
PCS50  1U_0402_25V6K  [C_0402]  146.46 142.64 0 top
PCS51  0.22U_0402_25V6K  [C_0402]  143.21 142.07 0 bottom
PCS52  1U_0402_25V6K  [C_0402]  146.14 147.74 270 top
PCS53  1U_0402_6.3V6K  [C_0402]  145.35 138.13 90 bottom
PCS54  1U_0402_6.3V6K  [C_0402]  147.33 147.33 270 top
PCS55  0.22U_0402_25V6K  [C_0402]  149.38 138.96 0 bottom
PCS56  560P_0402_50V7K  [C_0402]  152.05 143.02 0 top
PCS57  1000P_0402_50V7K  [C_0402]  152.31 142.2 0 bottom
PCS58  0.022U_0603_50V7K  [C_0603]  152.69 143.94 90 bottom
PCS61  22U_B2_25VM_R100M  [C_B2]  130.2 137.5 90 bottom
PCS62  22U_B2_25VM_R100M  [C_B2]  136.31 127.52 180 top
PCS67  1U_0402_25V6K  [C_0402]  124.41 144.85 0 top
PCS68  1U_0402_25V6K  [C_0402]  146.79 143.72 180 top
PCS69  0.022U_0603_50V7K  [C_0603]  115.47 167.61 90 bottom
PCS70  0.022U_0603_50V7K  [C_0603]  138.2 152.09 90 bottom
PCS71  10U_0603_25V6M  [C_0603]  107.28 145.94 270 bottom
PCS72  10U_0603_25V6M  [C_0603]  106.09 145.94 270 bottom
PCS73  10U_0603_25V6M  [C_0603]  130.33 140.9 180 top
PCS74  10U_0603_25V6M  [C_0603]  130.33 139.7 180 top
PCS75  10U_0603_25V6M  [C_0603]  127.82 138.32 180 bottom
PCS76  10U_0603_25V6M  [C_0603]  127.82 137.13 180 bottom
PCS77  10U_0603_25V6M  [C_0603]  138.91 124.06 90 top
PCS78  10U_0603_25V6M  [C_0603]  137.7 124.06 90 top
PCS79  680P_0603_50V7K  [C_0603]  113.46 138.9 270 top
PCS81  680P_0603_50V7K  [C_0603]  151.64 138.26 270 top
PCS82  0.022U_0603_50V7K  [C_0603]  146.71 161.12 90 bottom
PCS83  0.022U_0603_50V7K  [C_0603]  161.38 153.06 270 top
PCS84  0.01UF_0402_25V7K  [C_0402]  121.43 150.48 90 top
PCS85  0.01UF_0402_25V7K  [C_0402]  153.69 147.31 90 bottom
PCS2508  2200P_0402_50V7K  [C_0402]  110.28 156.22 90 bottom
PCS2509  2200P_0402_50V7K  [C_0402]  111.24 156.22 90 bottom
PCS2510  2200P_0402_50V7K  [C_0402]  133.02 129.31 270 bottom
PCS2511  2200P_0402_50V7K  [C_0402]  134.14 129.31 270 bottom
PCZ01  0.1U_0402_25V6  [C_0402]  57.08 32.18 90 bottom
PCZ02  47P_0402_50V8J~D  [C_0402]  57.95 29.02 180 top
PCZ03  1U_0402_16V6K  [C_0402]  62.37 30.95 0 bottom
PCZ04  0.22U_0603_25V7K  [C_0603]  62.43 32.59 0 bottom
PCZ05  330P_0402_50V7K  [C_0402]  61.13 25.64 90 top
PCZ06  1000P_0402_50V7K  [C_0402]  63.97 29.95 270 bottom
PCZ07  68P_0402_50V8J  [C_0402]  63.83 25.6 90 top
PCZ08  6800P_0402_25V7K  [C_0402]  63.83 24.72 180 top
PCZ09  1500P_0402_50V7K  [C_0402]  65.6 24.9 270 top
PCZ10  1200P_0402_50V7K  [C_0402]  64.7 23.96 90 top
PCZ11  0.01UF_0402_25V7K  [C_0402]  65.62 29.03 90 bottom
PCZ12  0.15U_0402_16V7K  [C_0402]  68.36 26.24 0 top
PCZ13  0.022U_0402_16V7K  [C_0402]  68.3 27.71 0 bottom
PCZ14  2200P_0402_50V7K  [C_0402]  67.42 27.02 180 top
PCZ15  .1U_0402_16V7K  [C_0402]  69.3 25.39 270 top
PCZ16  0.022U_0402_25V7K  [C_0402]  70.12 34.49 0 top
PCZ17  0.022U_0402_25V7K  [C_0402]  67.42 24.48 270 top
PCZ18  0.022U_0402_25V7K  [C_0402]  70.12 33.58 0 bottom
PCZ19  0.022U_0402_25V7K  [C_0402]  70.12 33.6 0 top
PCZ20  0.022U_0402_25V7K  [C_0402]  66.51 24.48 270 top
PCZ21  .1U_0402_16V7K  [C_0402]  72.02 33.53 270 bottom
PCZ22  0.22U_0402_25V6K  [C_0402]  72.02 34.49 0 top
PCZ23  0.022U_0402_16V7K  [C_0402]  72.02 34.48 0 bottom
PCZ24  2200P_0402_50V7K  [C_0402]  70.07 32.7 0 top
PCZ25  100P_0402_50V8J  [C_0402]  72.96 31.8 180 top
PCZ26  0.01UF_0402_25V7K  [C_0402]  67.82 32.38 180 bottom
PCZ27  330P_0402_50V7K  [C_0402]  70.98 28.75 180 bottom
PCZ28  1000P_0402_50V7K  [C_0402]  66.95 28.79 0 bottom
PCZ29  68P_0402_50V8J  [C_0402]  67.86 30.88 180 bottom
PCZ30  8200P_0402_25V7K  [C_0402]  72.97 29.97 180 top
PCZ31  1500P_0402_50V7K  [C_0402]  72.06 30.88 0 top
PD1  SM24_SOT23  [TP0610K-T1-E3_SOT23-3]  153.09 158.4 270 top
PD2  SM24_SOT23  [TP0610K-T1-E3_SOT23-3]  133.88 152.67 90 bottom
PD3  -  [TVNST52302AB0_SOT523-3]  71.21 11.01 270 top
PD4  -  [TVNST52302AB0_SOT523-3]  76.4 9.2 180 top
PD5  -  [BAS40CW_SOT323-3]  350.09 10.42 0 top
PD200  30MA_30V_0.5UA_0.4V_SOD323-2  [D_SOD323-2]  221.72 115.41 0 top
PD301  -  [BAS40CW_SOT323-3]  323.87 15.31 90 top
PD704  -  [BAT54CW_SOT323-3]  207.42 125.95 180 top
PD705  -  [SS5P10-M3-86A_TO277A3]  188.53 135.85 90 top
PD706  -  [BAT54CW_SOT323-3]  207.54 131.02 0 top
PD1201  -  [SX34_SMA2]  365.67 53.57 180 bottom
PDS01  RB751V-40_SOD323-2  [SDMK0340L-7-F_SOD323-2]  121.44 152.29 270 bottom
PDS02  RB751V-40_SOD323-2  [SDMK0340L-7-F_SOD323-2]  141.63 147.33 270 bottom
PDS03  -  [SMF4L22A_SOD123FL2]  119.89 151.69 270 top
PDS04  -  [SMF4L22A_SOD123FL2]  143.35 146.15 90 top
PDS705  RB751V-40_SOD323-2  [SDMK0340L-7-F_SOD323-2]  205.18 129.06 270 top
PDS706  -  [SMF4L22A_SOD123FL2]  150.09 121.61 270 top
PH1  100K_0402_1%_B25/50 4250K  [R_0402]  155.21 55.9 0 top
PHZ01  470K_0402_5%_B25/50 4700K  [R_0402]  62.1 23.69 90 top
PHZ02  10K +-5% 0402 B25/50 4250K  [R_0402]  139.95 18.72 90 bottom
PHZ03  10K +-5% 0402 B25/50 4250K  [R_0402]  116.87 22.95 180 bottom
PHZ04  470K_0402_5%_B25/50 4700K  [R_0402]  72.99 29.13 180 bottom
PJP101  -  [JUMP_43X39]  274.07 22.07 90 top
PJP102  -  [JUMP_43X118]  264.88 33.14 90 top
PJP103  -  [JUMP_43X118]  259.62 33.12 90 top
PJP200  -  [JUMP_43X118]  250.27 110.63 270 top
PJP201  -  [JUMP_43X118]  255.47 110.63 270 top
PJP202  -  [JUMP_43X39]  210.93 116.91 270 top
PJP203  -  [JUMP_43X39]  223.47 120.28 0 top
PJP301  -  [JUMP_43X118]  335.86 48.34 0 top
PJP302  -  [JUMP_43X118]  333.07 27.38 0 top
PJP303  -  [JUMP_43X118]  333.08 22.12 0 top
PJP304  -  [JUMP_43X118]  335.86 43.13 0 top
PJP1201  -  [JUMP_43X39]  370.05 49.53 180 bottom
PJP1202  -  [JUMP_43X39]  370.81 51.79 0 bottom
PJP1801  -  [JUMP_43X79]  294.32 36.87 270 top
PJP1802  -  [JUMP_43X79]  300.98 38.4 90 bottom
PJP2501  -  [JUMP_43X79]  242.22 12.04 0 bottom
PJP2502  -  [JUMP_43X79]  230.73 17.95 90 bottom
PJPA01  -  [JUMP_43X39]  133.83 121.44 0 top
PJPDC1  ACES_50493-01301-P01  [ACES_50493-01301-P01_13P]  137.22 159.58 0 bottom
PJPDC2  ACES_50493-01301-P01  [ACES_50493-01301-P01_13P]  131.19 159.65 180 top
PJPF01  -  [JUMP_43X39]  152.83 118.34 270 bottom
PJPF02  -  [JUMP_43X118]  161.34 106.19 0 bottom
PJPS01  JUMP_43X118  [JUMP_43X118-NPM]  116.07 150.94 270 top
PJPS02  JUMP_43X118  [JUMP_43X118-NPM]  112.15 151.15 180 top
PJPS03  JUMP_43X118  [JUMP_43X118-NPM]  134.25 136.42 180 top
PJPS04  JUMP_43X118  [JUMP_43X118-NPM]  138.36 136.62 270 top
PL1  5A_Z80_0805_2P  [5A_Z120_0805_2P]  121.59 159.97 90 top
PL2  5A_Z80_0805_2P  [5A_Z120_0805_2P]  119.81 159.97 90 top
PL3  5A_Z80_0805_2P  [5A_Z120_0805_2P]  125.07 163.24 180 top
PL4  5A_Z80_0805_2P  [5A_Z120_0805_2P]  123.37 159.97 90 top
PL5  5A_Z80_0805_2P  [5A_Z120_0805_2P]  125.07 165.02 180 top
PL6  BLM15HG601SN1D_2P  [MURAT_BLM15HG601SN1D_2P]  152.17 156.08 90 top
PL7  5A_Z80_0805_2P  [5A_Z120_0805_2P]  148.25 154.52 270 top
PL8  5A_Z80_0805_2P  [5A_Z120_0805_2P]  146.47 154.52 270 top
PL9  5A_Z80_0805_2P  [5A_Z120_0805_2P]  144.7 154.52 270 top
PL10  5A_Z80_0805_2P  [5A_Z120_0805_2P]  142.92 154.52 270 top
PL11  5A_Z80_0805_2P  [5A_Z120_0805_2P]  141.14 154.52 270 top
PL12  BLM15HG601SN1D_2P  [MURAT_BLM15HG601SN1D_2P]  132.25 154.33 0 bottom
PL13  9A Z80 10M 1812_2P  [9A_Z80_1812_2P]  67.59 22.48 270 bottom
PL14  9A Z80 10M 1812_2P  [9A_Z80_1812_2P]  71.38 22.47 270 bottom
PL101  1UH_11A_20%_7X7X3_M  [L_7X7X3_M_2P]  265.88 15.39 180 top
PL201  1UH_MMD-10CZN1R0M-R1L_20A_20%  [MAG_MMD-10CZN1R0M-R1L_2P]  252.59 117.17 180 top
PL301  1.5UH_MMD-10CZN1R5M-R1L_16A_20%  [MAG_MMD-10CZ-2R2M-X2L_2P]  322.05 51.15 180 top
PL302  1.5UH_MMD-10CZN1R5M-R1L_16A_20%  [MAG_MMD-10CZ-2R2M-X2L_2P]  314.8 28.95 0 top
PL311  5A_Z80_0805_2P  [5A_Z120_0805_2P]  307.12 37.13 0 top
PL312  5A_Z80_0805_2P  [5A_Z120_0805_2P]  307.12 35.35 0 top
PL700  2.2UH_12A_20%_10X10X4_M  [L_10X10X4_M_2P]  202.44 149.65 180 top
PL711  1UH_PCMB063T-1R0MS_12A_20%  [CYNTE_PCMB063T-1R0MS_2P]  187.04 148.34 90 top
PL1201  3.3UH_MMD-05CZ-3R3M-M7L_5A_20%  [MAG_MMD-05CZ-3R3M-M7L_2P]  365.92 49.43 180 bottom
PLA01  0.47UH_NA__12.2A_20%  [MAG_MMD05CZR47M_4P]  138.84 113.22 0 bottom
PLF01  1UH_PCMB042T-1R0MS_4.5A_20%  [CYNTE_PCMB042T-1R0MS_2P]  155.37 108.45 270 bottom
PLG01  0.15UH_MMD-06DZER15MEM1L_36A_20%  [L_7X7X4_M]  135.81 17.22 90 bottom
PLG02  0.15UH_MMD-06DZER15MEM1L_36A_20%  [L_7X7X4_M]  154.7 17.22 90 bottom
PLI01  0.22UH_MMD-06DZIR22MEM2L__32A_20%  [L_7X7X4_M]  112.57 35.71 0 bottom
PLI02  0.22UH_MMD-06DZIR22MEM2L__32A_20%  [L_7X7X4_M]  112.57 27.2 0 bottom
PLI03  0.22UH_MMD-06DZIR22MEM2L__32A_20%  [L_7X7X4_M]  119.48 57.96 90 bottom
PLI04  0.22UH_MMD-06DZIR22MEM2L__32A_20%  [L_7X7X4_M]  119.4 74.17 270 bottom
PLI05  0.22UH_MMD-06DZIR22MEM2L__32A_20%  [L_7X7X4_M]  112.63 43.74 0 bottom
PLI06  0.22UH_MMD-06DZIR22MEM2L__32A_20%  [L_7X7X4_M]  115.27 51.94 0 bottom
PLI11  9A Z80 10M 1812_2P  [KC_FBMA-L11-453215800LMA90T_2P]  108.69 93.51 270 bottom
PLI12  9A Z80 10M 1812_2P  [KC_FBMA-L11-453215800LMA90T_2P]  112.5 93.52 270 bottom
PLS01  1UH_MMD-10CZN1R0M-R1L_20A_20%  [MAG_MMD-10CZN1R0M-R1L_2P]  113.57 155.74 270 top
PLS02  1UH_SRPG1005-1R0M-AD_30A_20%  [MAGIC_SRPG1005-1R0M-AD_2P]  119.53 139.13 270 bottom
PLS04  1UH_SRPG1005-1R0M-AD_30A_20%  [MAGIC_SRPG1005-1R0M-AD_2P]  144.87 134.36 270 bottom
PLS10  1UH_MMD-10CZN1R0M-R1L_20A_20%  [MAG_MMD-10CZN1R0M-R1L_2P]  136.06 141 270 top
PQ1  FDV301N_G 1N SOT23-3  [FDV301N_NL_SOT23-3]  155.16 162.35 90 top
PQ2  MMST3904-7-F_SOT323-3  [RHU002N06_SOT323-3]  154.15 166.38 270 top
PQ3  FDV301N_G 1N SOT23-3  [FDV301N_NL_SOT23-3]  135.2 148.62 270 bottom
PQ4  MMST3904-7-F_SOT323-3  [RHU002N06_SOT323-3]  133.26 144.46 90 bottom
PQ6  L2N7002DW1T1G_SC88-6  [DMN65D8LDW-7_SOT363-6]  151.44 159.87 180 bottom
PQ7  L2N7002WT1G 1N SC-70-3  [SSM3K7002FU_SC70-3]  77.52 15.45 180 top
PQ8  -  [SI3457CDV-T1-GE3_TSOP6]  51.34 23.15 0 bottom
PQ9  L2N7002WT1G 1N SC-70-3  [SSM3K7002FU_SC70-3]  57.27 21.69 0 bottom
PQ10  L2N7002DW1T1G_SC88-6  [DMN65D8LDW-7_SOT363-6]  146.9 167.16 0 bottom
PQ11  L2N7002WT1G 1N SC-70-3  [SSM3K7002FU_SC70-3]  153.51 163.22 0 bottom
PQ12  L2N7002WT1G 1N SC-70-3  [SSM3K7002FU_SC70-3]  149.47 170.51 270 bottom
PQ101  -  [AON7408L_DFN8-5]  268.68 21.1 270 top
PQ102  -  [AON7752_DFN3X3EP8-5]  271.55 15.47 90 top
PQ200  -  [AON6380_DFN5X6-8-5]  234.02 114.77 90 top
PQ201  AON6354_N_DFN56-8-5  [AON6414AL_DFN8-5]  239.7 120.42 180 top
PQ202  L2N7002DW1T1G_SC88-6  [2N7002DW-7-F_SOT363-6]  215.67 108.85 90 top
PQ301  -  [AON7534_DFN3X3-8-5]  316.28 44.89 180 top
PQ302  -  [AON7508_DFN8-5]  321.02 43.05 90 top
PQ303  -  [AON7534_DFN3X3-8-5]  314.88 35.05 0 top
PQ304  -  [AON7508_DFN8-5]  321.3 35.12 90 top
PQ704  -  [PK5N2EA_PDFN5X6P8-5]  204.03 153.18 180 bottom
PQ708  -  [PK5N2EA_PDFN5X6P8-5]  193.81 152.55 0 bottom
PQ709  -  [LMUN5113T1G_SOT323-3]  201.9 127.65 0 top
PQ710  -  [LTC015EUBFS8TL_UMT3F]  201.84 131.49 90 top
PQ717  -  [EMB04N03H_EDFN5X6-8-5]  192.61 139.55 90 top
PQA01  AON6962_DFN5X6D-8-7  [AON6992_DFN5X6D-8-7]  138.62 116.95 90 bottom
PQS01  -  [AON6380_DFN5X6-8-5]  119 144.88 180 bottom
PQS02  -  [AON6380_DFN5X6-8-5]  115.18 134.94 0 top
PQS03  -  [AON6380_DFN5X6-8-5]  112.98 144.89 180 bottom
PQS04  -  [AON7380_DFN3X3-8-5]  123.25 136.88 180 top
PQS05  AON6314_N_DFN56-8-5  [Q_N_DFN56-8-5]  121.18 131.93 270 top
PQS06  -  [AON6380_DFN5X6-8-5]  149.93 132.48 90 top
PQS07  -  [AON6380_DFN5X6-8-5]  139.15 140.82 270 bottom
PQS08  -  [AON7380_DFN3X3-8-5]  141.87 127.33 270 top
PQS09  -  [AON6380_DFN5X6-8-5]  138.59 134.85 270 bottom
